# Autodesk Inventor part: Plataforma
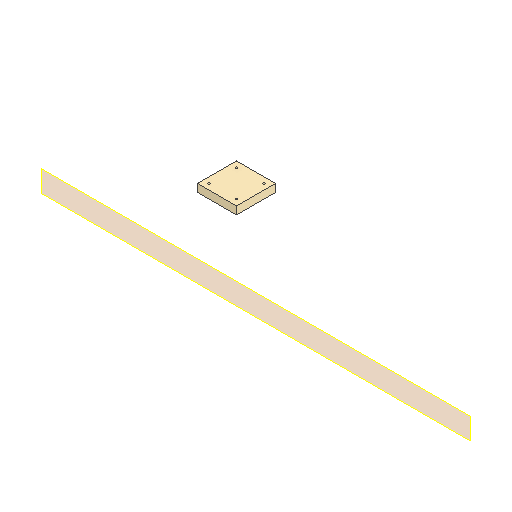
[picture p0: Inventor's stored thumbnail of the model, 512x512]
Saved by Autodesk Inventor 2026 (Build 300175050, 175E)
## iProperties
Created: 2025-04
Part Number: Plataforma
Material: Genérico
Document SubType Name: Modeling
Designer: piero
Density: 1 g/cm^3
Appearance: Valor por defecto
Author: piero
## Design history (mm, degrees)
node "Plano de trabajo2"
sketch "Boceto2"
  geometry: L1 (400, 250)-(500, 250); L2 (500, 250)-(500, 270); L3 (500, 270)-(400, 270); L4 (400, 270)-(400, 250); L5 (150, 50)-(150, 550) reference; L6 (0, 50)-(1000, 50) reference; L7 (850, 50)-(850, 550) reference; 1 further point
  constraints: 8 end point, 2 parallel, 1 horizontal, 1 perpendicular
  dimensions: "d4" = 100 distance of L3.end L2.end; "d5" = 20 distance of L2.end L1.end; "d6" = 250 distance between parallel lines of L5 L4; "d7" = 200 distance between parallel lines of L6 L1; "d8" = 350 distance between parallel lines of L7 L2 (derived)
extrude "Extrusión1" new body sketch "Boceto2" distance "d9" = 50; taper "d11" = 0 deg; dims "d10" = 50, "d12" = 0
sketch "Boceto3"
  geometry: L1 (0, 100)-(0, 0) reference; L2 (100, 100)-(100, 0) reference; L3 (0, 100)-(100, 100) reference; L4 (100, 0)-(0, 0) reference; C1 r 2.5 at (15, 15); C2 r 2.5 at (15, 85); C3 r 2.5 at (85, 85); C4 r 2.5 at (85, 15); 1 further point
  constraints: 4 centre point
  dimensions: "d13" = 5 diameter of C1; "d14" = 5 diameter of C2; "d15" = 5 diameter of C3; "d16" = 5 diameter of C4; "d17" = 15 distance from line of L1 C1.centre; "d18" = 15 distance from line of L1 C2.centre; "d19" = 15 distance from line of L2 C3.centre; "d20" = 15 distance from line of L2 C4.centre; "d21" = 15 distance from line of L3 C2.centre; "d22" = 15 distance from line of C3.centre L3; "d23" = 15 distance from line of L4 C1.centre; "d24" = 15 distance from line of L4 C4.centre
hole "Agujero1" sketch "Boceto3" diameter "d25" = 5; stored, may be unused: countersink angle "d29" = 90 deg, drill point angle "d31" = 118 deg; dims "d26" = 6, "d27" = 4, "d28" = 2, "d30" = 5
hole "Agujero2" sketch "Boceto3" diameter "d32" = 5; stored, may be unused: countersink angle "d36" = 90 deg, drill point angle "d38" = 118 deg; dims "d33" = 6, "d34" = 4, "d35" = 2, "d37" = 5
hole "Agujero3" sketch "Boceto3" diameter "d39" = 5; stored, may be unused: countersink angle "d43" = 90 deg, drill point angle "d45" = 118 deg; dims "d40" = 6, "d41" = 4, "d42" = 2, "d44" = 5
hole "Agujero4" sketch "Boceto3" diameter "d46" = 5; stored, may be unused: countersink angle "d50" = 90 deg, drill point angle "d52" = 118 deg; dims "d47" = 6, "d48" = 4, "d49" = 2, "d51" = 5
node "Sólido1"
node "Referencia4"
node "Referencia5"
node "Referencia6"
